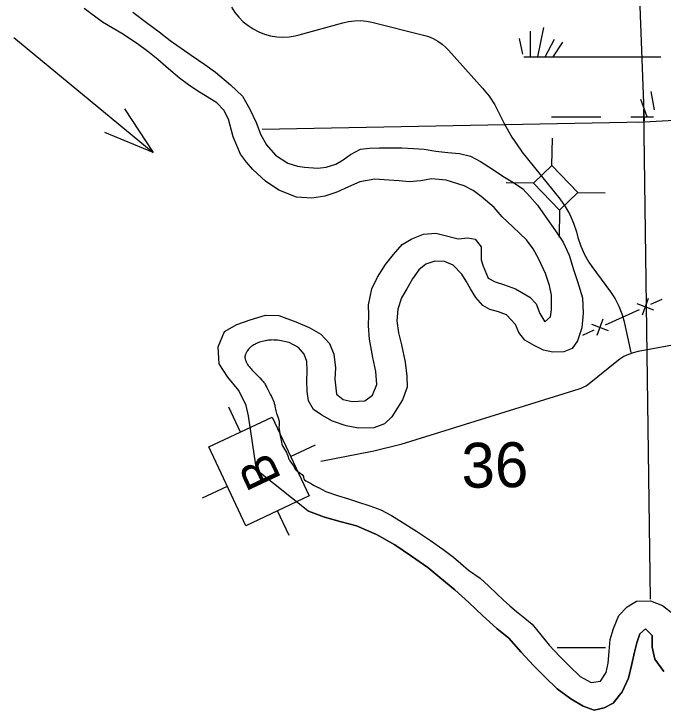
# Model space of a CAD drawing. Extents: x 2480962 to 2688785, y 277103 to 599240.
# Drawn here: x 2542062 to 2548571, y 527814 to 534793 of the extents above; entities that cross this region are included whole.
import ezdxf

# ---------------------------------------------------------------- set-up
doc = ezdxf.new("R2010")
doc.units = 0
for name, color, linetype in [('Culture', 7, 'Continuous'), ('Lakes and Ponds', 7, 'Continuous'), ('Local Roads Improved', 7, 'Continuous'), ('Narrow River Creek and Branch and Slough', 7, 'Continuous'), ('Section Lines', 7, 'Continuous'), ('Section Numbers', 7, 'Continuous'), ('Swamps', 7, 'Continuous'), ('Township and Range lines', 7, 'Continuous'), ('Uninventoried Roads and Features', 7, 'Continuous'), ('Wide Rivers and Canals Text', 7, 'Continuous')]:
    doc.layers.add(name, color=color, linetype=linetype)

msp = doc.modelspace()

# ---------------------------------------------------------------- linework, layer by layer
at = {"layer": 'Culture'}
for p, q in [((2544333.607, 530601.338), (2544216.579, 530850.177)), ((2544836.709, 530355.567), (2545085.563, 530472.603)), ((2543953.199, 529940.054), (2544202.052, 530057.089)), ((2544822.188, 529562.464), (2544705.153, 529811.317))]:
    msp.add_line(p, q, dxfattribs=at)
msp.add_lwpolyline([(2544387.824, 529662.078), (2544016.279, 530452.099), (2544650.937, 530750.577), (2545022.482, 529960.556)], close=True, dxfattribs=at)
at = {"layer": 'Lakes and Ponds'}
for points in [[(2543142.812, 534598.078), (2542948.305, 534711.548), (2542765.701, 534847.117)], [(2543253.9, 534809.016), (2543404.397, 534697.372), (2543518.779, 534611.641)], [(2544493.934, 530224.487), (2544413.412, 530763.455), (2544391.171, 530866.564), (2544318.503, 531018.619), (2544207.92, 531150.472), (2544119.321, 531286.425), (2544110.586, 531454.777), (2544171.924, 531607.378), (2544295.616, 531680.049), (2544431.422, 531726.71), (2544583.237, 531771.431), (2544719.261, 531767.977), (2544889.541, 531706.529), (2545021.801, 531648.934), (2545138.104, 531581.252), (2545224.519, 531487.387), (2545268.975, 531383.328), (2545285.58, 531245.078), (2545280.078, 531130.792), (2545296.734, 530980.514), (2545362.974, 530926.659), (2545453.066, 530906.98), (2545579.046, 530913.508), (2545658.796, 530971.968), (2545702.343, 531076.385), (2545689.775, 531206.635), (2545661.162, 531346.841), (2545628.355, 531531.132), (2545615.769, 531665.389), (2545619.306, 531771.649), (2545618.843, 531877.892), (2545652.153, 532036.393), (2545707.65, 532152.886), (2545789.103, 532279.51), (2545868.67, 532380.066), (2545956.237, 532480.654), (2546051.988, 532539.178), (2546169.802, 532583.761), (2546291.764, 532594.282), (2546371.855, 532574.562), (2546518.028, 532537.071), (2546611.981, 532549.482), (2546686.054, 532533.748), (2546748.389, 532457.826), (2546746.958, 532327.52), (2546767.239, 532263.455), (2546815.766, 532143.376), (2546885.935, 532105.575), (2546980.063, 532077.894), (2547090.251, 532036.247), (2547154.421, 531998.421), (2547236.626, 531952.65), (2547298.917, 531886.752), (2547335.348, 531788.674), (2547385.709, 531706.69), (2547441.502, 531755.029), (2547453.187, 531827.243), (2547452.549, 531973.578), (2547432.12, 532071.72), (2547391.593, 532191.832), (2547320.943, 532339.886), (2547268.412, 532439.089), (2547202.115, 532527.834), (2547063.532, 532659.574), (2546957.089, 532759.37), (2546876.674, 532853.26), (2546748.187, 532962.989), (2546665.911, 533020.959), (2546577.706, 533070.543), (2546397.452, 533125.937), (2546249.384, 533139.365), (2546141.466, 533118.878), (2546025.496, 533110.386), (2545923.452, 533118.643), (2545821.406, 533127.595), (2545681.355, 533137.047), (2545531.462, 533110.375), (2545415.683, 533057.783), (2545299.905, 533005.19), (2545180.074, 532964.609), (2545050.146, 532946.038), (2544896.095, 532955.432), (2544719.771, 533026.878), (2544583.38, 533114.525), (2544458.849, 533234.294), (2544392.387, 533306.741), (2544334.178, 533386.137), (2544261.406, 533562.246), (2544212.642, 533736.449), (2544166.014, 533827.875), (2544095.911, 533902.356), (2544000.6, 533961.203), (2543905.394, 534017.846), (2543813.042, 534082.096), (2543722.808, 534149.406), (2543613.197, 534242.987), (2543503.976, 534336.947), (2543403.897, 534417.296), (2543301.275, 534494.485), (2543142.812, 534598.078)], [(2543518.779, 534611.641), (2543629.16, 534525.892), (2543839.817, 534378.41), (2543976.236, 534284.749), (2544084.573, 534209.016), (2544233.139, 534081.327), (2544353.635, 533969.56), (2544428.208, 533839.564), (2544490.797, 533705.51), (2544537.34, 533581.413), (2544593.789, 533479.408), (2544686.24, 533377.55), (2544808.604, 533295.86), (2544904.74, 533266.183), (2544974.788, 533256.446), (2545108.838, 533246.97), (2545192.798, 533257.335), (2545288.672, 533287.796), (2545362.492, 533330.194), (2545438.26, 533384.628), (2545536.037, 533437.146), (2545625.998, 533447.537), (2545727.994, 533449.957), (2545823.999, 533450.35), (2545950.014, 533448.859), (2546068.046, 533443.327), (2546174.078, 533437.746), (2546292.171, 533418.182), (2546414.247, 533402.642), (2546528.297, 533393.085), (2546638.424, 533365.47), (2546740.657, 533313.766), (2546860.995, 533238.082), (2546965.315, 533166.341), (2547079.627, 533096.646), (2547165.885, 533038.864), (2547236.22, 532962.976), (2547310.609, 532875.076), (2547389.093, 532765.142), (2547493.736, 532619.232), (2547570.239, 532505.281), (2547630.819, 532373.223), (2547671.441, 532231.061), (2547713.976, 532108.953), (2547762.687, 531946.778), (2547771.36, 531792.458), (2547757.998, 531646.066), (2547712.564, 531515.581), (2547658.902, 531437.182), (2547575.038, 531404.766), (2547465.05, 531400.307), (2547370.949, 531421.974), (2547278.744, 531467.704), (2547186.494, 531523.457), (2547126.159, 531599.387), (2547089.807, 531679.423), (2546999.375, 531777.28), (2546919.248, 531805.018), (2546833.139, 531828.722), (2546764.961, 531868.536), (2546694.607, 531948.433), (2546640.22, 532036.415), (2546597.877, 532114.423), (2546551.569, 532184.395), (2546465.171, 532274.25), (2546379.01, 532309.982), (2546282.987, 532313.599), (2546191.114, 532283.155), (2546123.356, 532226.749), (2546057.746, 532136.274), (2546000.171, 532037.813), (2545946.562, 531947.386), (2545911.058, 531832.978), (2545901.574, 531714.666), (2545918.09, 531596.462), (2545946.625, 531474.297), (2545985.378, 531302.058), (2545999.991, 531161.794), (2546004.473, 531051.558), (2545957.03, 530923.069), (2545849.767, 530752.239), (2545778.061, 530683.789), (2545670.23, 530643.257), (2545516.231, 530640.624), (2545392.12, 530664.173), (2545255.904, 530711.728), (2545147.645, 530769.42), (2545065.387, 530827.218), (2545017, 530915.225), (2545002.598, 531007.378), (2544998.125, 531115.609), (2545003.697, 531213.858), (2544999.285, 531308.057), (2544972.961, 531382.121), (2544914.67, 531448.035), (2544822.447, 531497.774), (2544724.346, 531519.425)], [(2544724.346, 531519.425), (2544703.266, 531521.655), (2544682.128, 531523.213), (2544668.029, 531523.808), (2544649.248, 531523.964), (2544638.537, 531523.694), (2544626.324, 531523.034), (2544614.198, 531521.904), (2544602.134, 531520.261), (2544594.118, 531518.91), (2544583.456, 531516.824), (2544569.272, 531513.605), (2544550.381, 531508.692), (2544537.998, 531505.062), (2544525.87, 531501.054), (2544517.903, 531498.164), (2544507.401, 531494.029), (2544493.557, 531487.997), (2544485.702, 531484.274), (2544476.749, 531479.766), (2544466.525, 531474.271), (2544459.068, 531469.923), (2544451.986, 531465.36), (2544447.454, 531462.18), (2544441.621, 531457.748), (2544434.175, 531451.458), (2544430.065, 531447.645), (2544425.478, 531443.079), (2544420.355, 531437.564), (2544414.622, 531430.845), (2544408.177, 531422.576), (2544404.767, 531417.89), (2544399.36, 531409.929), (2544394.404, 531401.829), (2544391.386, 531396.369), (2544387.764, 531389.035), (2544385.917, 531384.826), (2544384.021, 531380.005), (2544382.15, 531374.491), (2544380.426, 531368.196), (2544379.038, 531361.029), (2544378.566, 531357.227), (2544378.279, 531353.19), (2544378.229, 531348.912), (2544378.48, 531344.385), (2544379.106, 531339.605), (2544380.467, 531332.833), (2544382.222, 531326.016), (2544383.605, 531321.458), (2544385.706, 531315.381), (2544388.947, 531307.307), (2544391.017, 531302.725), (2544393.568, 531297.529), (2544396.721, 531291.658), (2544400.619, 531285.06), (2544405.444, 531277.701), (2544411.414, 531269.575), (2544416.609, 531262.988), (2544421.795, 531256.564), (2544432.194, 531244.12), (2544439.192, 531236.062), (2544448.664, 531225.52), (2544461.67, 531211.647), (2544484.779, 531187.686), (2544507.882, 531163.724), (2544527.704, 531143.004), (2544547.3, 531122.063), (2544560.129, 531107.808), (2544567.18, 531099.235), (2544573.668, 531090.274), (2544577.729, 531084.116), (2544582.871, 531075.716), (2544589.354, 531064.254), (2544597.594, 531048.682), (2544608.481, 531027.82), (2544622.413, 531001.622), (2544635.92, 530975.321), (2544644.52, 530957.629), (2544655.28, 530933.725), (2544660.981, 530919.854), (2544667.026, 530903.773), (2544669.761, 530895.591), (2544672.203, 530887.331), (2544676.388, 530870.62), (2544678.808, 530859.381), (2544687.857, 530814.293), (2544690.909, 530801.554), (2544695.024, 530787.177), (2544697.57, 530779.611), (2544709.936, 530745.101), (2544722.297, 530710.59)], [(2545008.408, 529812.486), (2544500.083, 530216.398), (2544493.934, 530224.487), (2544493.934, 530224.487)], [(2545114.639, 530044.157), (2545188.986, 530003.825), (2545305.159, 529966.211), (2545415.312, 529932.582), (2545507.457, 529900.885), (2545631.638, 529861.298), (2545739.818, 529821.647), (2545849.329, 529763.765), (2545954.37, 529698.237), (2546097.267, 529606.306), (2546239.198, 529512.969), (2546363.58, 529427.278), (2546467.944, 529345.515), (2546543.292, 529281.727), (2546618.511, 529217.834), (2546736.875, 529136.128), (2546820.231, 529058.298), (2546903.565, 528980.448), (2546968.775, 528919.512), (2547034.104, 528858.698), (2547100.5, 528802.874), (2547168.592, 528748.993), (2547256.92, 528675.183), (2547345.387, 528569.299), (2547427.847, 528465.395), (2547534.358, 528349.562), (2547630.775, 528255.738), (2547741.243, 528149.944), (2547849.511, 528090.248), (2547943.462, 528102.658), (2547999.09, 528189.084), (2548020.671, 528285.394), (2548030.173, 528399.696), (2548041.641, 528522.025), (2548073.161, 528632.407), (2548126.596, 528762.925), (2548210.224, 528849.465), (2548305.992, 528903.981), (2548443.982, 528908.553), (2548566.198, 528860.941), (2548668.553, 528781.173)], [(2545015.826, 529808.671), (2545014.885, 529809.122), (2545013.943, 529809.573), (2545013.475, 529809.802), (2545013.01, 529810.038), (2545008.408, 529812.486)], [(2548579.075, 528201.474), (2548488.528, 528325.391), (2548462.003, 528445.559), (2548461.495, 528561.826), (2548395.204, 528627.708), (2548337.42, 528577.356), (2548307.802, 528489.032), (2548284.221, 528392.714), (2548254.796, 528260.29), (2548225.346, 528133.879), (2548161.937, 527997.305), (2548070.43, 527882.669), (2547980.627, 527836.196), (2547880.718, 527813.737), (2547768.547, 527851.368), (2547646.209, 527927.045), (2547507.765, 528026.71), (2547387.252, 528142.486), (2547270.722, 528262.288), (2547148.139, 528394.092), (2547025.521, 528533.916), (2546905.087, 528631.65), (2546760.502, 528763.365), (2546621.927, 528893.1), (2546481.369, 529018.817), (2546332.811, 529144.502), (2546212.376, 529242.237), (2546047.87, 529355.829), (2545881.363, 529469.412), (2545698.891, 529574.912), (2545498.506, 529660.293), (2545344.314, 529701.762), (2545176.105, 529747.181), (2545015.826, 529808.671)]]:
    msp.add_lwpolyline(points, dxfattribs=at)
msp.add_spline([(2544722.297, 530710.59), (2544720.503, 530629.956), (2544737.932, 530534.039), (2544755.36, 530464.281), (2544794.574, 530394.523), (2544812.003, 530350.924), (2544829.431, 530311.685), (2544864.288, 530263.726), (2544890.431, 530220.127), (2544964.501, 530154.729), (2544968.858, 530132.93), (2545016.787, 530098.051), (2545090.857, 530054.452), (2545104.995, 530048.089), (2545114.639, 530044.157)], degree=3, dxfattribs=at)
at = {"layer": 'Local Roads Improved'}
for p, q in [((2549105.26, 531552.019), (2548320.194, 531406.885)), ((2548106.649, 531308.728), (2547828.698, 531084.465)), ((2547726.776, 531030.143), (2545939.915, 530476.558)), ((2545636.682, 530401.015), (2545140.616, 530306.699))]:
    msp.add_line(p, q, dxfattribs=at)
for points in [[(2548320.194, 531406.885), (2548271.473, 531395.211), (2548224.238, 531378.509), (2548179.009, 531356.961), (2548136.28, 531330.803), (2548106.649, 531308.728)], [(2547828.698, 531084.465), (2547802.668, 531065.623), (2547774.811, 531049.606), (2547745.434, 531036.588), (2547726.776, 531030.143)], [(2545939.915, 530476.558), (2545658.027, 530405.159), (2545636.682, 530401.014)]]:
    msp.add_lwpolyline(points, dxfattribs=at)
at = {"layer": 'Narrow River Creek and Branch and Slough'}
for points in [[(2545008.408, 529812.486), (2545013.01, 529810.038), (2545013.475, 529809.802), (2545013.943, 529809.573), (2545014.885, 529809.122), (2545015.826, 529808.671)], [(2545015.826, 529808.671), (2545176.105, 529747.181), (2545344.314, 529701.762), (2545498.506, 529660.293), (2545698.891, 529574.912), (2545881.363, 529469.412), (2546047.87, 529355.829), (2546212.376, 529242.237), (2546332.811, 529144.502), (2546481.369, 529018.817), (2546621.927, 528893.1), (2546760.502, 528763.365), (2546905.087, 528631.65), (2547025.521, 528533.916), (2547148.139, 528394.092), (2547270.722, 528262.288), (2547387.252, 528142.486), (2547507.765, 528026.71), (2547646.209, 527927.045), (2547768.547, 527851.368), (2547880.718, 527813.737), (2547980.627, 527836.196), (2548070.43, 527882.669), (2548161.937, 527997.305), (2548225.346, 528133.879), (2548254.796, 528260.29), (2548284.221, 528392.714), (2548307.802, 528489.032), (2548337.42, 528577.356), (2548395.204, 528627.708), (2548461.495, 528561.826), (2548462.003, 528445.559), (2548488.528, 528325.391), (2548579.075, 528201.474)]]:
    msp.add_lwpolyline(points, dxfattribs=at)
at = {"layer": 'Section Lines'}
for p, q in [((2548323.592, 533709.154), (2553807.366, 534018.366)), ((2544550.968, 533637.277), (2548381.207, 533712.403))]:
    msp.add_line(p, q, dxfattribs=at)
at = {"layer": 'Swamps'}
for p, q in [((2547237.529, 534619.843), (2547237.533, 534361.282)), ((2547370.434, 534656.091), (2547311.497, 534361.388)), ((2547479.175, 534535.271), (2547385.17, 534360.684)), ((2547563.751, 534511.107), (2547464.434, 534362.127)), ((2548412.03, 533761.472), (2548346.556, 533933.336))]:
    msp.add_line(p, q, dxfattribs=at)
for points in [[(2547128.789, 534547.348), (2547160.58, 534388.4)], [(2547175.954, 534361.281), (2548547.208, 534361.301)], [(2548484.209, 533832.297), (2548450.848, 534015.765)], [(2547451.839, 533761.287), (2547946.595, 533761.294)], [(2548246.595, 533761.298), (2548475.755, 533761.302)]]:
    msp.add_lwpolyline(points, dxfattribs=at)
at = {"layer": 'Township and Range lines'}
for p, q in [((2548179.819, 539013.519), (2548381.075, 533722.43)), ((2548444.299, 528923.984), (2548379.574, 533836.309)), ((2547994.343, 528438.77), (2547508.959, 528437.404))]:
    msp.add_line(p, q, dxfattribs=at)
at = {"layer": 'Uninventoried Roads and Features'}
for p, q in [((2544920.533, 534582.932), (2545359.29, 534704.937)), ((2545651.206, 534709.069), (2546169.078, 534580.735)), ((2546418.948, 534430.632), (2546761.1, 534049.691)), ((2546915.783, 533819.863), (2546977.261, 533693.56)), ((2547456.846, 533273.279), (2547461.84, 533548.19)), ((2547155.861, 533411.399), (2547535.519, 532937.697)), ((2547456.846, 533273.279), (2547272.568, 533095.577)), ((2547717.152, 533003.341), (2547456.846, 533273.279)), ((2547272.568, 533095.577), (2546997.658, 533100.571)), ((2547272.568, 533095.577), (2547532.874, 532825.639)), ((2547532.874, 532825.639), (2547717.152, 533003.341)), ((2547717.152, 533003.341), (2547992.062, 532998.347)), ((2547532.908, 532827.536), (2547527.915, 532552.626)), ((2547701.576, 532609.142), (2547717.026, 532551.136)), ((2547856.894, 532260.226), (2548044.169, 532006.593)), ((2548309.282, 531888.062), (2548474.803, 531825.993)), ((2548423.077, 531939.788), (2548361.008, 531774.267)), ((2548448.94, 531882.891), (2548562.735, 531934.617)), ((2547993.76, 531675.985), (2548335.145, 531831.164)), ((2547854.102, 531681.156), (2548019.623, 531619.088)), ((2547967.897, 531732.883), (2547905.828, 531567.361)), ((2548180.711, 531704.43), (2548246.488, 531400.032)), ((2547766.17, 531572.532), (2547879.965, 531624.259))]:
    msp.add_line(p, q, dxfattribs=at)
for points in [[(2544244.495, 534860.167), (2544278.323, 534807.804), (2544317.44, 534759.265), (2544361.417, 534715.08), (2544409.77, 534675.733), (2544461.973, 534641.658), (2544517.45, 534613.225), (2544575.596, 534590.747), (2544635.774, 534574.47), (2544697.322, 534564.573), (2544759.569, 534561.163), (2544821.83, 534564.279), (2544883.426, 534573.885), (2544920.533, 534582.932)], [(2545359.29, 534704.937), (2545417.953, 534717.985), (2545477.658, 534724.83), (2545537.752, 534725.396), (2545597.575, 534719.678), (2545651.206, 534709.069)], [(2546169.078, 534580.735), (2546218.782, 534565.616), (2546266.633, 534545.385), (2546312.107, 534520.263), (2546354.706, 534490.526), (2546393.963, 534456.498), (2546418.948, 534430.632)], [(2546761.1, 534049.691), (2546826.664, 533968.522), (2546883.385, 533880.944), (2546915.783, 533819.863)], [(2546977.261, 533693.56), (2547053.421, 533555.905), (2547143.553, 533426.966), (2547155.861, 533411.399)], [(2547535.519, 532937.697), (2547590.065, 532861.819), (2547636.38, 532780.655), (2547673.958, 532695.095), (2547701.576, 532609.142)], [(2547717.026, 532551.136), (2547744.851, 532465.063), (2547781.521, 532382.369), (2547826.633, 532303.963), (2547856.893, 532260.226)], [(2548044.169, 532006.593), (2548089.703, 531937.645), (2548127.78, 531864.315), (2548157.984, 531787.406), (2548179.983, 531707.762), (2548180.711, 531704.43)]]:
    msp.add_lwpolyline(points, dxfattribs=at)
at = {"layer": 'Wide Rivers and Canals Text'}
msp.add_line((2542061.709, 534556.598), (2543458.42, 533402.836), dxfattribs=at)
msp.add_lwpolyline([(2543169.962, 533840.164), (2543458.42, 533402.836), (2542974.496, 533603.539)], dxfattribs=at)

# ---------------------------------------------------------------- texts
at = {"layer": 'Culture'}
msp.add_text('B', height=350, rotation=115.1874944, dxfattribs=at).set_placement((2544747.367, 530132.757))
at = {"layer": 'Section Numbers'}
msp.add_text('36', height=450, rotation=0.8220167, dxfattribs=at).set_placement((2546552.564, 530040.904))

doc.saveas('drawing.dxf')
